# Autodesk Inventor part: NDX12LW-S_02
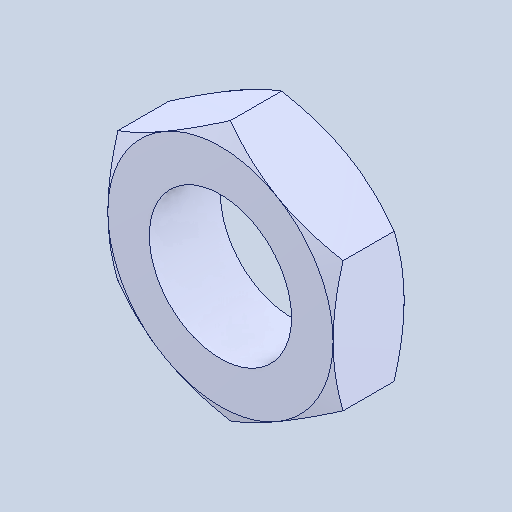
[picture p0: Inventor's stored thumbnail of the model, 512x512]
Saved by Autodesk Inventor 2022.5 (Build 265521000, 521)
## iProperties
Created: 2024-05
Part Number: NDX12LW-S_02
Material: 一般
Document SubType Name: Modeling
Designer: ImaoCorp
Density: 1 g/cm^3
Appearance: 既定
Author: ImaoCorp
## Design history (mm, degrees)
feature "NDX12LW-S_02"
node "ソリッド1"
